(* Logix 5000 project; controller V16_L55_Blank vendor 1 type 14 code 51 rev 16.2; software revision 16.04; part 5 of 5 *)
(* tags used below, declared in another part *)
   ErrorTimer : TIMER;
(* AOI69EAFCNetworkConfig, continued *)

ROUTINE Prescan   (* ladder *)
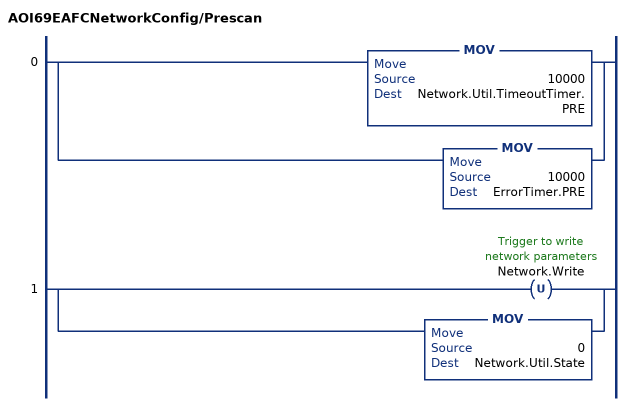
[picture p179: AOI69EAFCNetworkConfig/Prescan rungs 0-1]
   0: [MOV(10000,Network.Util.TimeoutTimer.PRE) ,MOV(10000,ErrorTimer.PRE) ];
   1: [OTU(Network.Write) ,MOV(0,Network.Util.State) ];
END_ROUTINE
END_ADD_ON_INSTRUCTION

VAR_GLOBAL   (* controller tags *)
   AFC : AFCEModuleDef;
   AFCMeter01DifferentialGas : AFCEMeterDifferentialGas;
   AFCMeter02DifferentialLiquid : AFCEMeterDifferentialLiquid;
   AFCMeter03LinearGas : AFCEMeterLinearGas;
   AFCMeter04LinearLiquid : AFCEMeterLinearLiquid;
   AOI69EAFC : AOI69EAFC;
   AOI69EAFCMeter01DifferentialGas : AOI69EAFCMeterDifferentialGas := (MeterNumber := 1);
   AOI69EAFCMeter02DifferentialLiquid : AOI69EAFCMeterDifferentialLiquid;
   AOI69EAFCMeter03LinearGas : AOI69EAFCMeterLinearGas;
   AOI69EAFCMeter04LinearLiquid : AOI69EAFCMeterLinearLiquid := (MeterNumber := 4);
   AOINetworkConfig : AOI69EAFCNetworkConfig;
   Network : AFCENetwork := (Config.Physical_Interface_IP[0] := 192, Config.Physical_Interface_IP[1] := 168, Config.Physical_Interface_IP[3] := 250, Config.Physical_Interface_Network_Prefix := 24, Config.Default_Gateway_IP[0] := 192, Config.Default_Gateway_IP[1] := 168, Config.Default_Gateway_IP[3] := 1, Config.Server1_Network_Prefix := 24, Config.Server1_MBAP_Port := 502, Config.Server1_Listener_IP[0] := 192, Config.Server1_Listener_IP[1] := 168, Config.Server1_Listener_IP[3] := 251);
END_VAR

PROGRAM MainProgram   (* main routine MainRoutine *)

ROUTINE MainRoutine   (* ladder *)
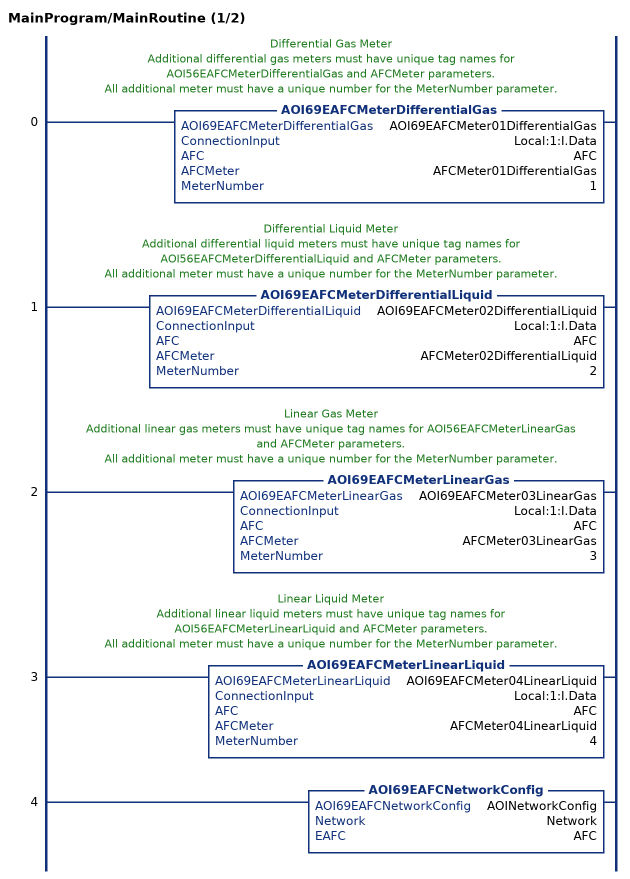
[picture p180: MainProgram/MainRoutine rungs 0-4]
   // Differential Gas Meter
   // Additional differential gas meters must have unique tag names for AOI56EAFCMeterDifferentialGas and AFCMeter parameters.
   // All additional meter must have a unique number for the MeterNumber parameter.
   0: AOI69EAFCMeterDifferentialGas(AOI69EAFCMeter01DifferentialGas,Local:1:I.Data,AFC,AFCMeter01DifferentialGas,1);
   // Differential Liquid Meter
   // Additional differential liquid meters must have unique tag names for AOI56EAFCMeterDifferentialLiquid and AFCMeter parameters.
   // All additional meter must have a unique number for the MeterNumber parameter.
   1: AOI69EAFCMeterDifferentialLiquid(AOI69EAFCMeter02DifferentialLiquid,Local:1:I.Data,AFC,AFCMeter02DifferentialLiquid,2);
   // Linear Gas Meter
   // Additional linear gas meters must have unique tag names for AOI56EAFCMeterLinearGas and AFCMeter parameters.
   // All additional meter must have a unique number for the MeterNumber parameter.
   2: AOI69EAFCMeterLinearGas(AOI69EAFCMeter03LinearGas,Local:1:I.Data,AFC,AFCMeter03LinearGas,3);
   // Linear Liquid Meter
   // Additional linear liquid meters must have unique tag names for AOI56EAFCMeterLinearLiquid and AFCMeter parameters.
   // All additional meter must have a unique number for the MeterNumber parameter.
   3: AOI69EAFCMeterLinearLiquid(AOI69EAFCMeter04LinearLiquid,Local:1:I.Data,AFC,AFCMeter04LinearLiquid,4);
   4: AOI69EAFCNetworkConfig(AOINetworkConfig,Network,AFC);
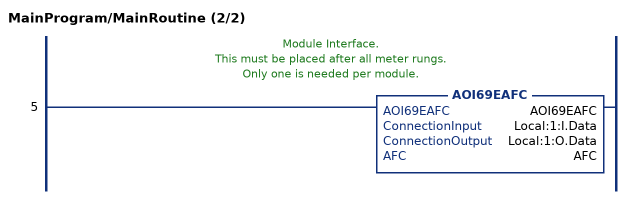
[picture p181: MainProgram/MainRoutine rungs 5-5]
   // Module Interface.
   // This must be placed after all meter rungs.
   // Only one is needed per module.
   5: AOI69EAFC(AOI69EAFC,Local:1:I.Data,Local:1:O.Data,AFC);
END_ROUTINE
END_PROGRAM
